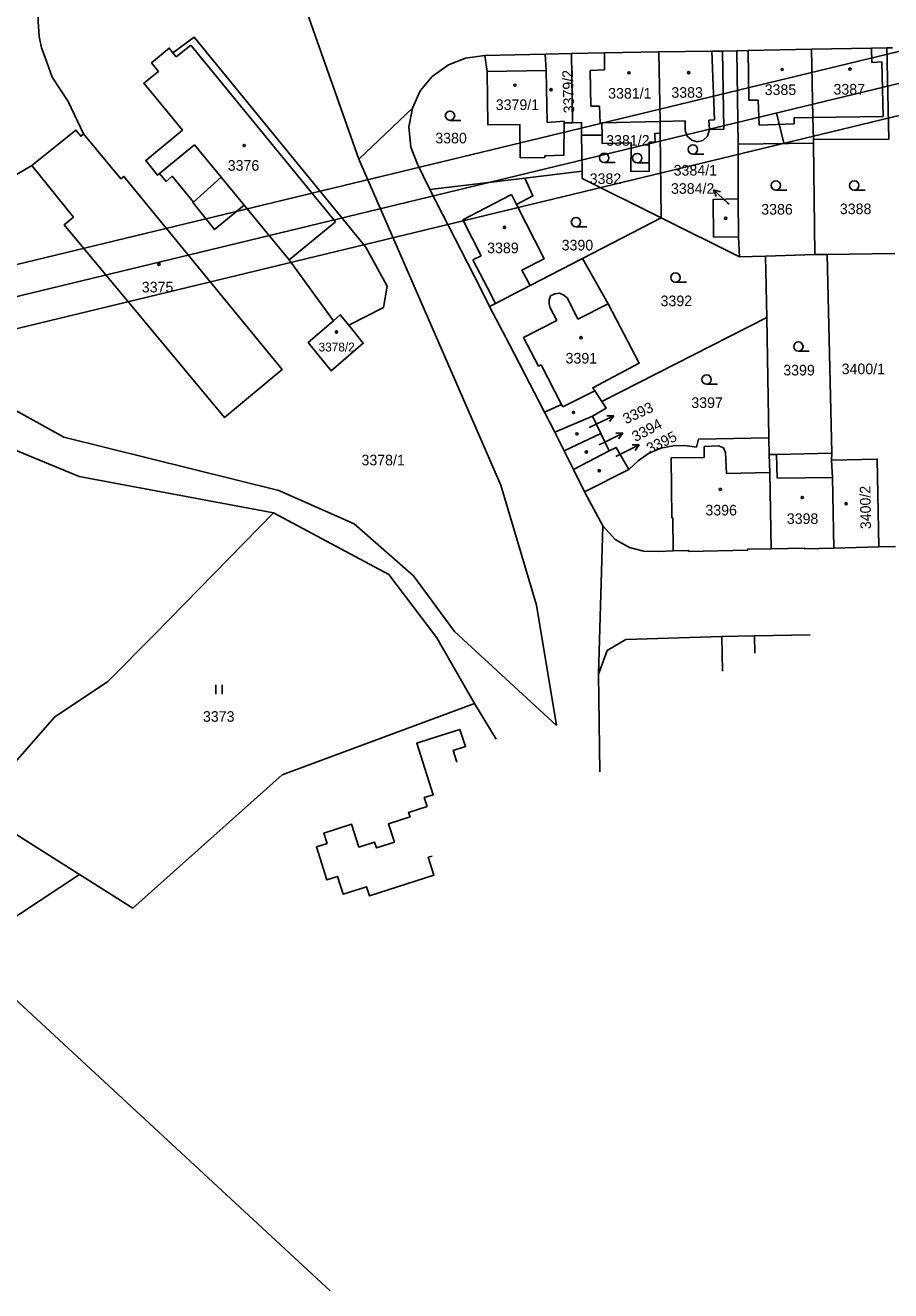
# Model space of a CAD drawing. Extents: x -738085 to -734306, y -1122197 to -1119753.
# Drawn here: x -734994.5 to -734855.7, y -1120555.7 to -1120352.8 of the extents above; entities that cross this region are included whole.
import ezdxf

# ---------------------------------------------------------------- set-up
doc = ezdxf.new("R2010")
doc.units = 0
for name, color, linetype in [('Hranice parcel', 7, 'Continuous'), ('Parcelní čísla', 7, 'Continuous'), ('Pop  PČ popisy', 7, 'Continuous'), ('Vnitřní kresba', 7, 'Continuous'), ('Vrstva 1', 7, 'Continuous'), ('Značky budov', 7, 'Continuous'), ('Značky kultur', 7, 'Continuous')]:
    doc.layers.add(name, color=color, linetype=linetype)

msp = doc.modelspace()

# ---------------------------------------------------------------- linework, layer by layer
at = {"layer": 'Hranice parcel'}
for p, q in [((-734920.79, -1120357.62), (-734911.1, -1120357.39)), ((-734911.1, -1120357.39), (-734906.87, -1120357.29)), ((-734906.7, -1120368.42), (-734906.87, -1120357.29)), ((-734892.68, -1120368.2), (-734892.88, -1120357.06)), ((-734882.67, -1120356.91), (-734880.38, -1120356.87)), ((-734880.38, -1120356.87), (-734880.17, -1120371.86)), ((-734856.27, -1120356.4), (-734855.37, -1120356.38)), ((-734985.19, -1120370.19), (-734987.62, -1120364.99)), ((-734941, -1120374.24), (-734932.39, -1120366.1)), ((-734892.65, -1120370.11), (-734892.68, -1120368.2)), ((-734908.07, -1120368.45), (-734906.7, -1120368.42)), ((-734892.47, -1120383.67), (-734892.65, -1120370.11)), ((-734905.26, -1120370.43), (-734901.98, -1120370.38)), ((-734905.18, -1120376.19), (-734905.26, -1120370.43)), ((-734880.17, -1120371.86), (-734868.06, -1120371.71)), ((-734880.17, -1120371.86), (-734880.15, -1120380.63)), ((-734868.06, -1120371.71), (-734868.07, -1120371.08)), ((-734867.82, -1120389.56), (-734868.06, -1120371.71)), ((-735019.26, -1120390.39), (-734993.45, -1120375.29)), ((-734914.38, -1120377.29), (-734905.18, -1120376.19)), ((-734929.59, -1120379.11), (-734914.38, -1120377.29)), ((-734880.07, -1120386.71), (-734880.15, -1120380.63)), ((-734905.09, -1120390.18), (-734892.47, -1120383.67)), ((-734879.91, -1120389.93), (-734892.47, -1120383.67)), ((-734880.07, -1120386.71), (-734879.91, -1120389.93)), ((-734913.52, -1120394.53), (-734905.09, -1120390.18)), ((-734879.91, -1120389.93), (-734875.76, -1120389.8)), ((-734875.76, -1120389.8), (-734867.82, -1120389.56)), ((-734875.57, -1120399.65), (-734875.76, -1120389.8)), ((-734867.82, -1120389.56), (-734865.85, -1120389.53)), ((-734865.85, -1120389.53), (-734855.03, -1120389.39)), ((-734865.11, -1120421.41), (-734865.85, -1120389.53)), ((-734902.01, -1120413.11), (-734875.57, -1120399.65)), ((-734875.57, -1120399.65), (-734875.2, -1120418.95)), ((-734909.54, -1120418.05), (-734903.52, -1120415.44)), ((-734902.17, -1120418.23), (-734903.52, -1120415.44)), ((-734909.54, -1120418.05), (-734908.05, -1120421.02)), ((-734908.05, -1120421.02), (-734902.17, -1120418.23)), ((-734900.82, -1120421.02), (-734902.17, -1120418.23)), ((-734875.2, -1120418.95), (-734875.15, -1120421.63)), ((-734908.05, -1120421.02), (-734906.55, -1120424.02)), ((-734906.55, -1120424.02), (-734900.82, -1120421.02)), ((-734865.17, -1120422.51), (-734865.11, -1120421.41)), ((-734906.55, -1120424.02), (-734904.77, -1120427.58)), ((-734904.77, -1120427.58), (-734897.68, -1120424.04)), ((-734904.77, -1120427.58), (-734901.85, -1120433.04)), ((-734901.85, -1120433.04), (-734902.54, -1120456.85)), ((-734864.81, -1120436.62), (-734857.6, -1120436.44)), ((-734857.6, -1120436.44), (-734854.88, -1120436.34)), ((-734882.75, -1120450.79), (-734882.68, -1120456.34)), ((-734902.54, -1120456.85), (-734902.33, -1120472.51)), ((-734918.98, -1120467.25), (-734922.46, -1120461.53)), ((-734985.79, -1120488.96), (-735000.7, -1120479.57)), ((-734998.42, -1120497.31), (-734985.79, -1120488.96)), ((-734985.79, -1120488.96), (-734977.27, -1120494.33))]:
    msp.add_line(p, q, dxfattribs=at)
for points in [[(-734987.62, -1120364.99), (-734990.19, -1120361.1), (-734991.31, -1120357.96), (-734991.92, -1120356.42), (-734992.3, -1120354.58), (-734992.44, -1120352.17), (-734992.41, -1120350.36), (-734991.84, -1120347.81), (-734990.65, -1120344.99), (-734989.08, -1120342.62), (-734987.01, -1120340.42), (-734984.73, -1120338.93), (-734983.2, -1120337.99)], [(-734983.2, -1120337.99), (-734949.91, -1120348.95), (-734941, -1120374.24)], [(-734942.62, -1120400.88), (-734937.04, -1120398.06), (-734936.47, -1120394.6), (-734939.86, -1120388.34), (-734967.4, -1120354.71), (-734970.83, -1120357.18), (-734971.42, -1120356.44), (-734974.24, -1120358.8), (-734973.15, -1120360.18), (-734975.49, -1120362.07), (-734969.3, -1120369.59), (-734975.18, -1120374.44), (-734973.29, -1120376.82), (-734972.97, -1120376.56), (-734971.92, -1120377.82), (-734970.93, -1120377), (-734967.5, -1120381.15), (-734967.59, -1120381.23), (-734964.14, -1120385.51), (-734959.4, -1120381.62), (-734952.16, -1120390.42), (-734945.07, -1120400.15)], [(-734932.39, -1120366.1), (-734931.13, -1120363.27), (-734929.21, -1120361), (-734926.63, -1120359.15), (-734923.89, -1120358.05), (-734920.79, -1120357.62)], [(-734920.79, -1120357.62), (-734920.42, -1120360.2), (-734920.28, -1120368.73), (-734915.17, -1120368.67), (-734915.1, -1120374.03), (-734911.16, -1120373.98), (-734911.16, -1120373.74), (-734908.13, -1120373.63), (-734908.07, -1120368.45)], [(-734908.07, -1120368.45), (-734908.07, -1120368.17), (-734910.77, -1120368.35), (-734910.93, -1120360.02), (-734911.1, -1120357.39)], [(-734906.87, -1120357.29), (-734901.6, -1120357.2), (-734892.88, -1120357.06)], [(-734892.88, -1120357.06), (-734884.35, -1120356.93), (-734882.67, -1120356.91)], [(-734884.73, -1120369.49), (-734882.45, -1120369.43), (-734882.67, -1120356.91)], [(-734880.38, -1120356.87), (-734878.55, -1120356.83), (-734868.36, -1120356.63)], [(-734868.36, -1120356.63), (-734858.77, -1120356.45), (-734856.27, -1120356.4)], [(-734868.07, -1120371.08), (-734868.15, -1120367.57), (-734868.36, -1120356.63)], [(-734868.07, -1120371.08), (-734855.97, -1120371.03), (-734856.27, -1120356.4)], [(-734932.39, -1120366.1), (-734932.96, -1120369.05), (-734932.67, -1120372.33), (-734931.61, -1120375.07), (-734929.59, -1120379.11)], [(-734901.98, -1120370.38), (-734902.03, -1120368.45), (-734892.68, -1120368.2)], [(-734892.68, -1120368.2), (-734888.67, -1120368.1), (-734888.64, -1120369.67)], [(-734985.19, -1120370.19), (-734985.6, -1120370.57), (-734986.39, -1120369.59), (-734993.45, -1120375.29)], [(-734993.45, -1120375.29), (-734986.77, -1120383.54), (-734988.24, -1120384.76), (-734962.52, -1120415.7), (-734953.28, -1120407.96), (-734978.69, -1120377.03), (-734979.15, -1120377.41), (-734985.19, -1120370.19)], [(-734905.26, -1120370.43), (-734905.29, -1120368.37), (-734906.7, -1120368.42)], [(-734901.98, -1120370.38), (-734901.94, -1120371.76), (-734897.32, -1120371.63), (-734897.35, -1120376.23), (-734894.42, -1120376.19), (-734894.4, -1120371.54), (-734893.47, -1120371.51), (-734893.51, -1120370.13), (-734892.65, -1120370.11)], [(-734888.64, -1120369.67), (-734888.3, -1120370.59), (-734887.59, -1120371.22), (-734886.73, -1120371.45), (-734885.8, -1120371.25), (-734885.09, -1120370.55), (-734884.73, -1120369.49)], [(-734941, -1120374.24), (-734918.24, -1120426.53), (-734912.49, -1120445.79), (-734909.31, -1120465.06)], [(-734905.18, -1120376.19), (-734905.16, -1120377.33), (-734892.47, -1120383.67)], [(-734913.52, -1120394.53), (-734914.85, -1120392.07), (-734911.26, -1120390.23), (-734915.68, -1120381.54), (-734913.07, -1120380.15), (-734914.38, -1120377.29)], [(-734920.01, -1120397.87), (-734921.29, -1120395.37), (-734923.59, -1120390.85), (-734929.59, -1120379.11)], [(-734880.15, -1120380.63), (-734884.17, -1120380.72), (-734884.08, -1120386.77), (-734880.07, -1120386.71)], [(-734909.31, -1120465.06), (-734925.64, -1120449.97), (-734932.2, -1120441.06), (-734941.76, -1120432.71), (-734953.85, -1120427.36), (-734988.31, -1120418.81), (-735000.61, -1120412.05), (-735019.26, -1120390.39)], [(-734902.01, -1120413.11), (-734903.15, -1120411.4), (-734903.48, -1120410.9), (-734896.03, -1120406.99), (-734900.98, -1120397.47), (-734905.09, -1120390.18)], [(-734920.01, -1120397.87), (-734919.06, -1120397.38), (-734913.52, -1120394.53)], [(-734954.71, -1120430.95), (-734985.85, -1120425.14), (-734996.33, -1120420.82), (-735006.01, -1120414.59), (-735019.86, -1120396.91)], [(-734920.01, -1120397.87), (-734916.83, -1120403.99), (-734911.22, -1120414.81), (-734909.54, -1120418.05)], [(-734945.07, -1120400.15), (-734949.11, -1120403.66), (-734945.45, -1120408.17), (-734940.29, -1120403.76), (-734942.62, -1120400.88)], [(-734945.07, -1120400.15), (-734943.98, -1120399.21), (-734942.62, -1120400.88)], [(-734903.52, -1120415.44), (-734901.3, -1120414.17), (-734902.01, -1120413.11)], [(-734897.68, -1120424.04), (-734899.69, -1120420.47), (-734900.82, -1120421.02)], [(-734890.56, -1120420.2), (-734892.55, -1120420.6), (-734894.55, -1120421.47)], [(-734886.83, -1120420.45), (-734888.69, -1120420.18), (-734890.56, -1120420.2)], [(-734875.2, -1120418.95), (-734886.5, -1120419.14), (-734886.83, -1120420.45)], [(-734894.55, -1120421.47), (-734896.17, -1120422.63), (-734897.68, -1120424.04)], [(-734865.11, -1120421.41), (-734873.97, -1120421.61), (-734875.15, -1120421.63)], [(-734875.15, -1120421.63), (-734875.09, -1120424.52), (-734874.85, -1120436.75)], [(-734865.17, -1120422.51), (-734857.82, -1120422.33), (-734857.6, -1120436.44)], [(-734864.81, -1120436.62), (-734865.03, -1120425.29), (-734865.17, -1120422.51)], [(-734998.72, -1120473.9), (-734989.84, -1120463.71), (-734981.27, -1120457.99), (-734973.79, -1120450.49), (-734954.71, -1120430.95)], [(-734922.46, -1120461.53), (-734928.46, -1120451), (-734936.19, -1120440.85), (-734954.71, -1120430.95)], [(-734874.85, -1120436.75), (-734878.63, -1120436.81), (-734878.63, -1120436.95), (-734888.09, -1120437.15), (-734888.09, -1120437), (-734890.55, -1120437.07), (-734892.88, -1120437.14), (-734895.35, -1120437.12), (-734897.6, -1120436.52), (-734899.86, -1120435.24), (-734901.85, -1120433.04)], [(-734874.85, -1120436.75), (-734869.49, -1120436.61), (-734869.49, -1120436.71), (-734864.81, -1120436.62)], [(-734902.54, -1120456.85), (-734901.17, -1120453.01), (-734898.14, -1120451.26), (-734882.75, -1120450.79)], [(-734882.75, -1120450.79), (-734877.53, -1120450.7), (-734868.61, -1120450.54)], [(-734977.27, -1120494.33), (-734953.29, -1120472.96), (-734922.46, -1120461.53)], [(-734929.22, -1120486), (-734929.86, -1120486.2), (-734928.96, -1120489.04), (-734939.31, -1120492.37), (-734939.76, -1120490.93), (-734943.49, -1120492.12), (-734944.4, -1120489.27), (-734946.11, -1120489.81), (-734947.81, -1120484.51), (-734946.09, -1120483.96), (-734946.62, -1120482.35), (-734942.17, -1120480.91), (-734940.99, -1120484.56), (-734938.46, -1120483.76), (-734938.16, -1120484.69), (-734935.3, -1120483.76), (-734936.23, -1120480.81), (-734932.78, -1120479.7), (-734933.01, -1120478.99), (-734930.04, -1120478.05), (-734930.5, -1120476.62), (-734929.05, -1120476.18), (-734931.07, -1120469.9), (-734931.71, -1120467.9), (-734929.56, -1120467.2), (-734924.77, -1120465.68), (-734923.87, -1120468.42), (-734925.86, -1120469.07), (-734925.26, -1120470.94)], [(-734945.57, -1120555.69), (-735000, -1120505.42), (-735005.87, -1120500), (-735013.7, -1120492.77)]]:
    msp.add_lwpolyline(points, dxfattribs=at)
at = {"layer": 'Pop  PČ popisy'}
for p, q in [((-734881.88, -1120381.23), (-734884.08, -1120379.18)), ((-734884.08, -1120379.18), (-734883, -1120379.5)), ((-734884.08, -1120379.18), (-734883.68, -1120380.23)), ((-734881.61, -1120381.47), (-734881.88, -1120381.23)), ((-734904.07, -1120417.29), (-734902.8, -1120416.69)), ((-734902.8, -1120416.69), (-734900.08, -1120415.42)), ((-734900.08, -1120415.42), (-734901.2, -1120415.39)), ((-734900.08, -1120415.42), (-734900.78, -1120416.3)), ((-734901.33, -1120419.53), (-734898.66, -1120418.17)), ((-734898.66, -1120418.17), (-734899.78, -1120418.18)), ((-734898.66, -1120418.17), (-734899.32, -1120419.07)), ((-734902.43, -1120420.08), (-734901.33, -1120419.53)), ((-734898.71, -1120421.4), (-734896.01, -1120420.08)), ((-734896.01, -1120420.08), (-734897.13, -1120420.07)), ((-734896.01, -1120420.08), (-734896.69, -1120420.97)), ((-734899.75, -1120421.91), (-734898.71, -1120421.4))]:
    msp.add_line(p, q, dxfattribs=at)
at = {"layer": 'Vnitřní kresba'}
for p, q in [((-734970.3, -1120357.86), (-734967.96, -1120355.97)), ((-734967.96, -1120355.97), (-734944.72, -1120384.32)), ((-734970.83, -1120357.18), (-734970.3, -1120357.86)), ((-734901.6, -1120357.2), (-734901.56, -1120359.95)), ((-734884.35, -1120356.93), (-734883.95, -1120367.97)), ((-734878.55, -1120356.83), (-734878.41, -1120364.8)), ((-734858.77, -1120356.45), (-734858.72, -1120358.76)), ((-734920.42, -1120360.2), (-734910.93, -1120360.02)), ((-734903.86, -1120360.02), (-734901.56, -1120359.95)), ((-734903.86, -1120360.02), (-734903.8, -1120365.77)), ((-734858.72, -1120358.76), (-734857.11, -1120358.63)), ((-734857.11, -1120358.63), (-734856.88, -1120367.41)), ((-734903.8, -1120365.77), (-734902.38, -1120365.76)), ((-734902.38, -1120365.76), (-734902.28, -1120368.46)), ((-734878.41, -1120364.8), (-734876.91, -1120364.77)), ((-734876.91, -1120364.77), (-734876.77, -1120368.79)), ((-734884.87, -1120368), (-734883.95, -1120367.97)), ((-734884.87, -1120368), (-734884.73, -1120369.49)), ((-734871.17, -1120367.61), (-734868.15, -1120367.57)), ((-734871.17, -1120367.61), (-734871.16, -1120368.59)), ((-734868.15, -1120367.57), (-734856.88, -1120367.41)), ((-734902.28, -1120368.46), (-734902.03, -1120368.45)), ((-734876.77, -1120368.79), (-734871.16, -1120368.59)), ((-734972.97, -1120376.56), (-734967.38, -1120371.93)), ((-734967.38, -1120371.93), (-734963.09, -1120377.13)), ((-734967.5, -1120381.15), (-734963.09, -1120377.13)), ((-734963.09, -1120377.13), (-734959.4, -1120381.62)), ((-734924.32, -1120383.97), (-734916.51, -1120379.91)), ((-734916.51, -1120379.91), (-734915.68, -1120381.54)), ((-734952.16, -1120390.42), (-734944.72, -1120384.32)), ((-734924.32, -1120383.97), (-734921.38, -1120389.77)), ((-734922.73, -1120390.41), (-734921.38, -1120389.77)), ((-734922.73, -1120390.41), (-734920.37, -1120394.9)), ((-734920.37, -1120394.9), (-734919.06, -1120397.38)), ((-734910.45, -1120396.8), (-734910.23, -1120396.17)), ((-734910.23, -1120396.17), (-734909.58, -1120395.83)), ((-734909.58, -1120395.83), (-734908.82, -1120395.74)), ((-734908.82, -1120395.74), (-734908.1, -1120396.06)), ((-734908.1, -1120396.06), (-734907.54, -1120396.53)), ((-734907.54, -1120396.53), (-734905.87, -1120399.93)), ((-734910.46, -1120397.47), (-734910.45, -1120396.8)), ((-734910.46, -1120397.47), (-734910.31, -1120398.08)), ((-734910.31, -1120398.08), (-734909.25, -1120400.14)), ((-734905.87, -1120399.93), (-734900.98, -1120397.47)), ((-734914.58, -1120402.83), (-734909.25, -1120400.14)), ((-734914.58, -1120402.83), (-734912.17, -1120407.43)), ((-734912.17, -1120407.43), (-734911.77, -1120407.23)), ((-734911.77, -1120407.23), (-734908.5, -1120413.57)), ((-734908.29, -1120413.97), (-734903.15, -1120411.4)), ((-734911.22, -1120414.81), (-734908.5, -1120413.57)), ((-734908.5, -1120413.57), (-734908.29, -1120413.97)), ((-734885.62, -1120420.31), (-734883.29, -1120420.23)), ((-734885.62, -1120420.31), (-734885.6, -1120422.08)), ((-734883.29, -1120420.23), (-734882.48, -1120420.55)), ((-734882.48, -1120420.55), (-734882.17, -1120421.28)), ((-734890.9, -1120422.14), (-734885.6, -1120422.08)), ((-734890.9, -1120422.14), (-734890.77, -1120431.78)), ((-734882.17, -1120421.28), (-734882.04, -1120424.65)), ((-734873.97, -1120421.61), (-734873.89, -1120425.43)), ((-734882.04, -1120424.65), (-734875.09, -1120424.52)), ((-734873.89, -1120425.43), (-734865.03, -1120425.29)), ((-734890.77, -1120431.78), (-734890.62, -1120431.77)), ((-734890.62, -1120431.77), (-734890.55, -1120437.07)), ((-734877.53, -1120450.7), (-734877.48, -1120453.44))]:
    msp.add_line(p, q, dxfattribs=at)
at = {"layer": 'Vrstva 1'}
msp.add_line((-734873.98, -1120366.82), (-734872.81, -1120371.68), dxfattribs=at)
for points in [[(-734534.27, -1119984.39), (-735554.91, -1120230.88), (-735485.2, -1120519.57), (-734464.55, -1120273.08)], [(-734470.58, -1120269.4), (-735481.51, -1120513.53), (-735548.88, -1120234.56), (-734537.95, -1119990.43)], [(-734541.63, -1119996.45), (-735348.44, -1120191.3), (-735283.42, -1120460.56), (-734476.61, -1120265.71)]]:
    msp.add_lwpolyline(points, close=True, dxfattribs=at)
at = {"layer": 'Značky budov'}
for centre in [(-734873.08, -1120359.88), (-734862.21, -1120359.81), (-734897.66, -1120360.4), (-734888.09, -1120360.38), (-734915.95, -1120362.39), (-734910.17, -1120363.11), (-734959.39, -1120372.06), (-734882.15, -1120383.75), (-734917.64, -1120385.17), (-734973.06, -1120391.13), (-734944.58, -1120401.98), (-734905.35, -1120402.87), (-734906.56, -1120414.88), (-734905.99, -1120418.29), (-734904.49, -1120421.22), (-734902.43, -1120424.21), (-734883.01, -1120427.21), (-734869.86, -1120428.5), (-734862.81, -1120429.49)]:
    msp.add_circle(centre, 0.175, dxfattribs=at)
at = {"layer": 'Značky kultur'}
for p, q in [((-734926.37, -1120368.03), (-734924.62, -1120368.03)), ((-734887.41, -1120373.43), (-734885.66, -1120373.43)), ((-734901.62, -1120374.81), (-734899.87, -1120374.81)), ((-734896.33, -1120374.82), (-734894.58, -1120374.82)), ((-734874.1, -1120379.21), (-734872.35, -1120379.21)), ((-734861.52, -1120379.22), (-734859.77, -1120379.22)), ((-734906.16, -1120385.09), (-734904.41, -1120385.09)), ((-734890.2, -1120393.98), (-734888.45, -1120393.98)), ((-734870.49, -1120405.06), (-734868.74, -1120405.06)), ((-734885.21, -1120410.35), (-734883.46, -1120410.35)), ((-734963.91, -1120460.02), (-734963.91, -1120458.52)), ((-734962.91, -1120460.02), (-734962.91, -1120458.52))]:
    msp.add_line(p, q, dxfattribs=at)
for centre in [(-734926.37, -1120367.28), (-734887.41, -1120372.68), (-734901.62, -1120374.06), (-734896.33, -1120374.07), (-734874.1, -1120378.46), (-734861.52, -1120378.47), (-734906.16, -1120384.34), (-734890.2, -1120393.23), (-734870.49, -1120404.31), (-734885.21, -1120409.6)]:
    msp.add_circle(centre, 0.75, dxfattribs=at)

# ---------------------------------------------------------------- texts
at = {"layer": 'Parcelní čísla'}
for s, rotation, p in [('3379/2', 92, (-734906.43, -1120366.86)), ('3393', 25, (-734898.15, -1120416.78)), ('3394', 28, (-734896.62, -1120419.64)), ('3395', 26, (-734894.33, -1120421.52)), ('3400/2', 91, (-734858.82, -1120433.57))]:
    msp.add_text(s, height=1.7, rotation=rotation, dxfattribs=at).set_placement(p)
for s, height, p in [('3381/1', 1.7, (-734901, -1120364.54)), ('3383', 1.7, (-734890.86, -1120364.41)), ('3385', 1.7, (-734875.89, -1120363.96)), ('3387', 1.7, (-734864.85, -1120363.89)), ('3379/1', 1.7, (-734919.03, -1120366.37)), ('3380', 1.7, (-734928.73, -1120371.72)), ('3381/2', 1.7, (-734901.31, -1120372.1)), ('3376', 1.7, (-734962.03, -1120376.11)), ('3384/1', 1.7, (-734890.49, -1120376.88)), ('3382', 1.7, (-734903.96, -1120378.23)), ('3384/2', 1.7, (-734890.92, -1120379.81)), ('3386', 1.7, (-734876.44, -1120383.14)), ('3388', 1.7, (-734863.83, -1120383.07)), ('3389', 1.7, (-734920.41, -1120389.33)), ('3390', 1.7, (-734908.46, -1120388.89)), ('3375', 1.7, (-734975.81, -1120395.62)), ('3392', 1.7, (-734892.59, -1120397.82)), ('3378/2', 1.419, (-734947.45, -1120405.09)), ('3391', 1.7, (-734907.83, -1120407.02)), ('3399', 1.7, (-734872.91, -1120408.93)), ('3400/1', 1.7, (-734863.54, -1120408.73)), ('3397', 1.7, (-734887.66, -1120414.15)), ('3378/1', 1.7, (-734940.57, -1120423.35)), ('3396', 1.7, (-734885.4, -1120431.38)), ('3398', 1.7, (-734872.34, -1120432.74)), ('3373', 1.7, (-734966, -1120464.47))]:
    msp.add_text(s, height=height, dxfattribs=at).set_placement(p)

doc.saveas('drawing.dxf')
